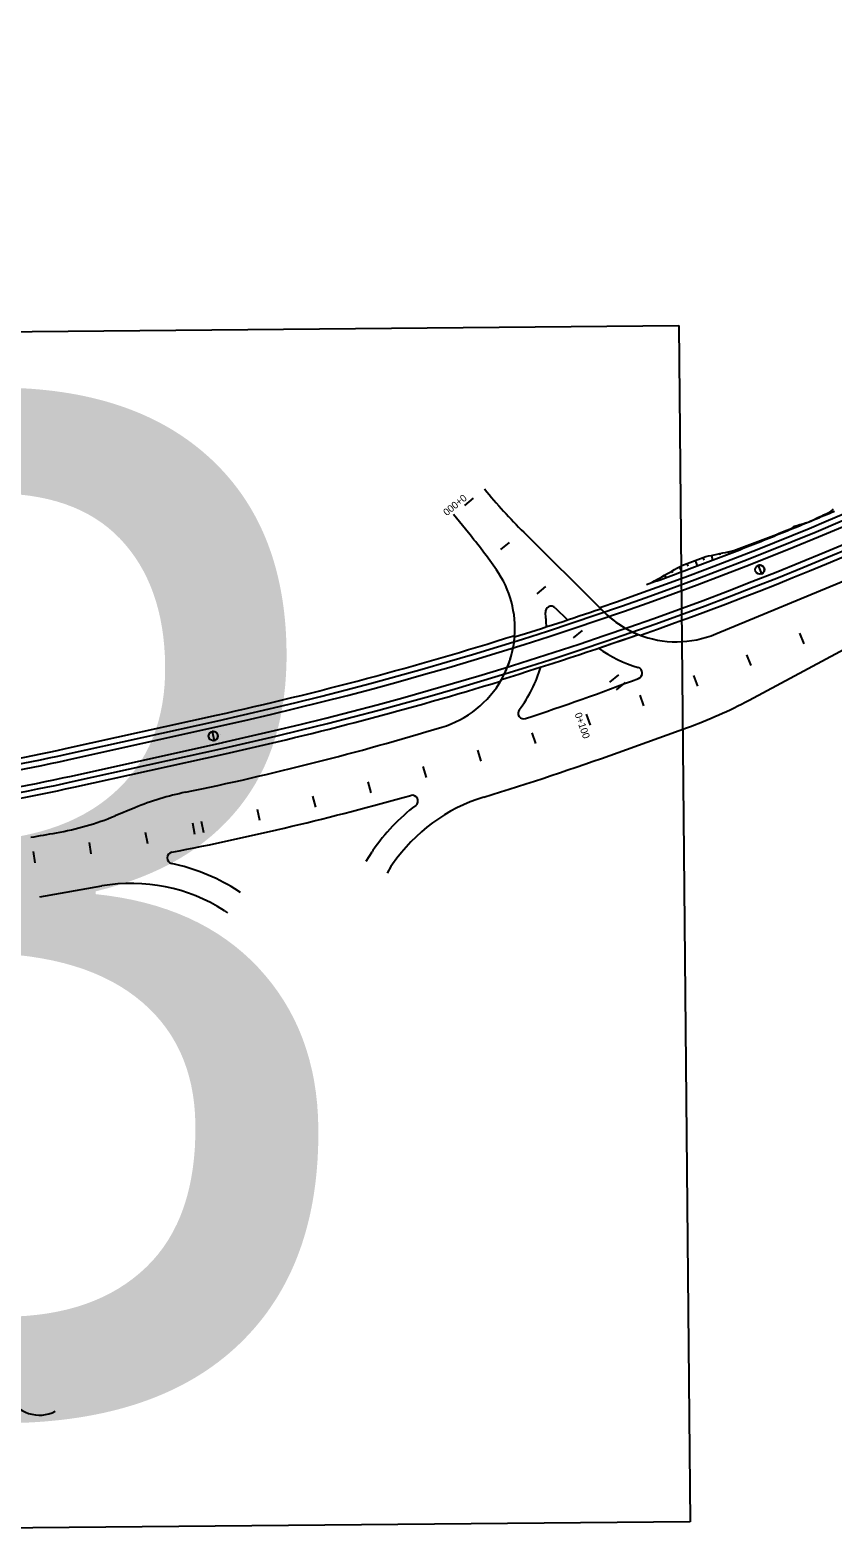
# Model space of a CAD drawing. Extents: x 6503541 to 6503743, y 5888004 to 5888145.
# Drawn here: x 6503677.06 to 6503680.42, y 5888078.09 to 5888084.41 of the extents above; entities that cross this region are included whole.
import ezdxf

# ---------------------------------------------------------------- set-up
doc = ezdxf.new("R2010")
doc.units = 0
doc.layers.add('12', color=7, linetype='Continuous')
doc.layers.add('tabela', color=7, linetype='Continuous')

msp = doc.modelspace()

# ---------------------------------------------------------------- linework, layer by layer
at = {"layer": '12'}
for p, q in [((6503678.8956, 5888082.3049), (6503678.8321, 5888082.3821)), ((6503680.3734, 5888082.3723), (6503680.3725, 5888082.3745)), ((6503680.4059, 5888082.3881), (6503680.4066, 5888082.3863)), ((6503680.2226, 5888082.3114), (6503680.2221, 5888082.3125)), ((6503680.2553, 5888082.3263), (6503680.2563, 5888082.3238)), ((6503680.2884, 5888082.3388), (6503680.2879, 5888082.3403)), ((6503680.3209, 5888082.3504), (6503680.3209, 5888082.3504)), ((6503679.1275, 5888082.3076), (6503679.4502, 5888081.987)), ((6503680.0541, 5888082.2479), (6503680.0558, 5888082.2434)), ((6503680.0886, 5888082.2586), (6503680.0878, 5888082.2606)), ((6503680.1214, 5888082.2735), (6503680.1228, 5888082.2699)), ((6503680.1556, 5888082.2848), (6503680.155, 5888082.2864)), ((6503680.1886, 5888082.2994), (6503680.1896, 5888082.2967)), ((6503679.8468, 5888082.1894), (6503679.8553, 5888082.1664)), ((6503679.8842, 5888082.1903), (6503679.8805, 5888082.2019)), ((6503679.9153, 5888082.211), (6503679.92, 5888082.1909)), ((6503679.9521, 5888082.2111), (6503679.9505, 5888082.2184)), ((6503679.9857, 5888082.226), (6503679.9879, 5888082.2169)), ((6503680.0212, 5888082.2327), (6503680.0204, 5888082.2352)), ((6503679.7175, 5888082.1271), (6503679.723, 5888082.1173)), ((6503679.753, 5888082.1374), (6503679.7488, 5888082.1449)), ((6503679.7801, 5888082.1627), (6503679.7903, 5888082.1421)), ((6503679.8176, 5888082.1654), (6503679.813, 5888082.1769)), ((6503679.6874, 5888082.1071), (6503679.6861, 5888082.1094)), ((6503679.9332, 5888081.8811), (6503680.4945, 5888082.1135)), ((6503679.259, 5888081.9908), (6503679.3104, 5888081.9398)), ((6503679.4502, 5888081.987), (6503679.4644, 5888081.9728)), ((6503679.4502, 5888081.987), (6503679.4626, 5888081.9746)), ((6503679.4502, 5888081.987), (6503679.4634, 5888081.9738)), ((6503680.0728, 5888081.6033), (6503680.5923, 5888081.8819)), ((6503677.2039, 5888081.3999), (6503677.8386, 5888081.5403)), ((6503677.2091, 5888081.3764), (6503677.8438, 5888081.5169)), ((6503677.2143, 5888081.353), (6503677.849, 5888081.4935)), ((6503679.5231, 5888081.3838), (6503679.8144, 5888081.4884)), ((6503677.2293, 5888081.285), (6503677.864, 5888081.4255)), ((6503677.2345, 5888081.2616), (6503677.8692, 5888081.4021)), ((6503677.2397, 5888081.2382), (6503677.8744, 5888081.3787)), ((6503677.4958, 5888081.1518), (6503677.4127, 5888081.1178)), ((6503678.4667, 5888080.9283), (6503678.4908, 5888080.9675)), ((6503678.4942, 5888080.9725), (6503678.4908, 5888080.9675)), ((6503678.5701, 5888080.905), (6503678.5539, 5888080.8773)), ((6503678.5773, 5888080.9154), (6503678.5701, 5888080.905)), ((6503677.097, 5888080.7782), (6503677.357, 5888080.8237)), ((6503677.9389, 5888080.7964), (6503677.9148, 5888080.8114)), ((6503677.8717, 5888080.7194), (6503677.8711, 5888080.7197)), ((6503677.8717, 5888080.7194), (6503677.8841, 5888080.7114))]:
    msp.add_line(p, q, dxfattribs=at)
for points in [[(6503678.9155, 5888082.4508), (6503678.8785, 5888082.4203)], [(6503679.6431, 5888082.0884), (6503679.6543, 5888082.0924), (6503679.6655, 5888082.0965), (6503679.6767, 5888082.1005), (6503679.6879, 5888082.1046), (6503679.6991, 5888082.1086), (6503679.7103, 5888082.1127), (6503679.7215, 5888082.1168), (6503679.7327, 5888082.1209), (6503679.7439, 5888082.125), (6503679.7551, 5888082.1291), (6503679.7663, 5888082.1332), (6503679.7774, 5888082.1373), (6503679.7886, 5888082.1415), (6503679.7998, 5888082.1456), (6503679.811, 5888082.1498), (6503679.8221, 5888082.1539), (6503679.8333, 5888082.1581), (6503679.8444, 5888082.1623), (6503679.8556, 5888082.1665), (6503679.8667, 5888082.1707), (6503679.8779, 5888082.1749), (6503679.889, 5888082.1791), (6503679.9002, 5888082.1833), (6503679.9113, 5888082.1875), (6503679.9224, 5888082.1918), (6503679.9336, 5888082.196), (6503679.9447, 5888082.2003), (6503679.9558, 5888082.2046), (6503679.9669, 5888082.2088), (6503679.978, 5888082.2131), (6503679.9891, 5888082.2174), (6503680.0003, 5888082.2217), (6503680.0114, 5888082.226), (6503680.0225, 5888082.2304), (6503680.0336, 5888082.2347), (6503680.0447, 5888082.239), (6503680.0557, 5888082.2434), (6503680.0668, 5888082.2477), (6503680.0779, 5888082.2521), (6503680.089, 5888082.2565), (6503680.1001, 5888082.2609), (6503680.1111, 5888082.2653), (6503680.1222, 5888082.2697), (6503680.1333, 5888082.2741), (6503680.1443, 5888082.2785), (6503680.1554, 5888082.2829), (6503680.1665, 5888082.2874), (6503680.1775, 5888082.2918), (6503680.1886, 5888082.2963), (6503680.1996, 5888082.3007), (6503680.2107, 5888082.3052), (6503680.2217, 5888082.3097), (6503680.2327, 5888082.3142), (6503680.2438, 5888082.3187), (6503680.2548, 5888082.3232), (6503680.2658, 5888082.3277), (6503680.2768, 5888082.3322), (6503680.2878, 5888082.3368), (6503680.2989, 5888082.3413), (6503680.3099, 5888082.3458), (6503680.3209, 5888082.3504), (6503680.3319, 5888082.355), (6503680.3429, 5888082.3596), (6503680.3539, 5888082.3641), (6503680.3649, 5888082.3687), (6503680.3758, 5888082.3733), (6503680.3868, 5888082.378), (6503680.3978, 5888082.3826)], [(6503680.3209, 5888082.3504), (6503680.3317, 5888082.3554), (6503680.3425, 5888082.3605), (6503680.3533, 5888082.3655), (6503680.3641, 5888082.3706), (6503680.3749, 5888082.3756), (6503680.3857, 5888082.3807), (6503680.3965, 5888082.3858), (6503680.4073, 5888082.3908), (6503680.4126, 5888082.3936)], [(6503680.3978, 5888082.3826), (6503680.4088, 5888082.3872), (6503680.4198, 5888082.3918), (6503680.4307, 5888082.3965)], [(6503680.4126, 5888082.3936), (6503680.4179, 5888082.3963), (6503680.4272, 5888082.4049)], [(6503679.6541, 5888082.093), (6503679.6651, 5888082.0976), (6503679.6757, 5888082.1035), (6503679.6862, 5888082.1095), (6503679.6967, 5888082.1154), (6503679.7072, 5888082.1213), (6503679.7177, 5888082.1272), (6503679.7282, 5888082.1332), (6503679.7387, 5888082.1391), (6503679.7492, 5888082.1451), (6503679.7597, 5888082.1511), (6503679.7702, 5888082.157), (6503679.7806, 5888082.163), (6503679.7911, 5888082.1689), (6503679.8023, 5888082.173), (6503679.8135, 5888082.1771), (6503679.8246, 5888082.1812), (6503679.8358, 5888082.1853), (6503679.847, 5888082.1894), (6503679.8581, 5888082.1936), (6503679.8692, 5888082.1977), (6503679.8804, 5888082.2019), (6503679.8916, 5888082.206), (6503679.9033, 5888082.2084), (6503679.9151, 5888082.2109), (6503679.9269, 5888082.2134), (6503679.9387, 5888082.2159), (6503679.9505, 5888082.2184), (6503679.9623, 5888082.2209), (6503679.974, 5888082.2235), (6503679.9858, 5888082.226), (6503679.9976, 5888082.2286), (6503680.0094, 5888082.2311), (6503680.0206, 5888082.2353), (6503680.0317, 5888082.2394), (6503680.0429, 5888082.2436), (6503680.054, 5888082.2478), (6503680.0651, 5888082.252), (6503680.0763, 5888082.2563), (6503680.0874, 5888082.2605), (6503680.0985, 5888082.2647), (6503680.1097, 5888082.269), (6503680.1208, 5888082.2732), (6503680.1319, 5888082.2775), (6503680.143, 5888082.2818), (6503680.1542, 5888082.286), (6503680.1653, 5888082.2903), (6503680.1764, 5888082.2946), (6503680.1875, 5888082.299), (6503680.1986, 5888082.3033), (6503680.2097, 5888082.3076), (6503680.2208, 5888082.3119), (6503680.2319, 5888082.3163), (6503680.243, 5888082.3206), (6503680.254, 5888082.3252), (6503680.2636, 5888082.333), (6503680.2751, 5888082.3364), (6503680.2865, 5888082.3399), (6503680.298, 5888082.3434), (6503680.3094, 5888082.3469), (6503680.3209, 5888082.3504)], [(6503679.031, 5888082.235), (6503679.0681, 5888082.2655)], [(6503680.1108, 5888082.1688), (6503680.1248, 5888082.1331)], [(6503679.1836, 5888082.0497), (6503679.2207, 5888082.0803)], [(6503679.3361, 5888081.8645), (6503679.3732, 5888081.895)], [(6503680.3043, 5888081.8402), (6503680.2856, 5888081.8844)], [(6503680.0818, 5888081.7489), (6503680.0641, 5888081.7935)], [(6503679.4887, 5888081.6792), (6503679.5258, 5888081.7097)], [(6503679.5524, 5888081.6774), (6503679.5153, 5888081.6469)], [(6503679.8576, 5888081.6621), (6503679.8407, 5888081.707)], [(6503679.6318, 5888081.5796), (6503679.6156, 5888081.6248)], [(6503679.3898, 5888081.5439), (6503679.4058, 5888081.4987)], [(6503677.8202, 5888081.4711), (6503677.8285, 5888081.4336)], [(6503679.1782, 5888081.4209), (6503679.1631, 5888081.4664)], [(6503678.9493, 5888081.3475), (6503678.935, 5888081.3933)], [(6503678.7189, 5888081.2785), (6503678.7056, 5888081.3246)], [(6503678.4873, 5888081.2139), (6503678.4748, 5888081.2603)], [(6503678.2544, 5888081.1538), (6503678.2429, 5888081.2004)], [(6503678.0205, 5888081.0982), (6503678.0099, 5888081.145)], [(6503677.5496, 5888081.0006), (6503677.5408, 5888081.0478)], [(6503677.7479, 5888081.0399), (6503677.7391, 5888081.0871)], [(6503677.7855, 5888081.0472), (6503677.7758, 5888081.0942)], [(6503677.3129, 5888080.9586), (6503677.3049, 5888081.0059)], [(6503677.0683, 5888080.9686), (6503677.0754, 5888080.9211)]]:
    msp.add_lwpolyline(points, dxfattribs=at)
for centre in [(6503680.1178, 5888082.151), (6503677.8244, 5888081.4524)]:
    msp.add_circle(centre, 0.0192, dxfattribs=at)
for centre, radius, start, end in [((6503674.6145, 5888096.105), 14.9412, 282.48188, 335.91738), ((6503674.6145, 5888096.105), 14.9652, 282.48188, 335.91738), ((6503674.6145, 5888096.105), 15.0348, 282.48188, 335.91738), ((6503674.6145, 5888096.105), 15.0588, 282.48188, 335.91738), ((6503674.6145, 5888096.105), 14.9172, 288.89877, 308.11483), ((6503674.6145, 5888096.105), 15.0828, 289.37027, 307.81474), ((6503680.8193, 5888084.0099), 2.4, 219.31239, 225.17753), ((6503677.0428, 5888080.7794), 2.4, 34.82086, 39.46694), ((6503678.6584, 5888081.9032), 0.432, 355.3769, 34.82086), ((6503680.1178, 5888082.151), 0.0192, 347.07645, 111.52368), ((6503680.1178, 5888082.151), 0.0192, 291.52368, 347.07645), ((6503679.2421, 5888081.9738), 0.024, 45.17753, 186.90027), ((6503679.7672, 5888082.281), 0.432, 222.00494, 249.66641), ((6503674.6145, 5888096.105), 14.9232, 287.44754, 288.90731), ((6503674.6145, 5888096.105), 14.9232, 287.44754, 288.90731), ((6503678.6584, 5888081.9032), 0.564, 0.7904, 6.90027), ((6503679.768, 5888082.2802), 0.432, 225.17753, 248.23474), ((6503674.6145, 5888096.105), 14.9172, 282.48188, 287.45669), ((6503678.6584, 5888081.9032), 0.432, 329.35412, 356.23305), ((6503674.6145, 5888096.105), 15.0768, 287.04736, 289.34339), ((6503674.6145, 5888096.105), 15.0768, 287.04736, 289.34087), ((6503678.6584, 5888081.9032), 0.432, 330.52309, 355.3769), ((6503679.768, 5888082.2802), 0.432, 248.23474, 292.49122), ((6503679.7672, 5888082.281), 0.564, 234.58535, 253.55389), ((6503678.6584, 5888081.9032), 0.564, 322.91658, 343.39971), ((6503679.6007, 5888081.7171), 0.024, 290.75597, 73.55389), ((6503674.6145, 5888096.105), 15.0828, 282.48188, 287.02283), ((6503678.6584, 5888081.9032), 0.432, 286.82524, 330.52309), ((6503675.2162, 5888093.2861), 12.396, 288.42954, 290.75597), ((6503675.2162, 5888093.2861), 12.396, 288.42954, 290.75597), ((6503679.1275, 5888081.5486), 0.024, 142.91658, 288.42954), ((6503679.1654, 5888083.2954), 1.92, 289.75621, 298.20181), ((6503675.2162, 5888093.2861), 12.324, 281.66639, 286.82524), ((6503677.8244, 5888081.4524), 0.0192, 338.03464, 102.48188), ((6503677.8244, 5888081.4524), 0.0192, 282.48188, 338.03464), ((6503675.6657, 5888088.3488), 7.1412, 272.95394, 282.48188), ((6503675.6645, 5888088.3538), 7.1223, 273.51736, 282.48188), ((6503675.2466, 5888093.2907), 12.6516, 287.06608, 289.75621), ((6503675.6657, 5888088.3488), 7.1652, 272.95394, 282.48188), ((6503675.6657, 5888088.3488), 7.2348, 272.95394, 282.48188), ((6503675.6657, 5888088.3488), 7.2588, 272.95394, 282.48188), ((6503675.6657, 5888088.3488), 7.2828, 273.57139, 282.48188), ((6503677.9509, 5888080.0415), 1.2, 101.66639, 112.28688), ((6503675.2466, 5888093.2907), 12.558, 281.03427, 285.73926), ((6503679.1708, 5888080.5079), 0.72, 107.06608, 145.52266), ((6503678.6596, 5888081.1804), 0.024, 307.23962, 105.73926), ((6503676.9576, 5888082.2281), 1.2, 280.00627, 292.28688), ((6503679.1708, 5888080.5079), 0.8208, 127.23962, 145.52266), ((6503674.1365, 5888098.2171), 17.436, 279.65062, 280.00627), ((6503677.6548, 5888080.9413), 0.024, 101.03427, 258.13958), ((6503677.4811, 5888080.1145), 0.8208, 58.10446, 78.13958), ((6503677.4811, 5888080.1145), 0.72, 57.20304, 99.92715), ((6503677.095, 5888078.7471), 0.144, 205.67836, 297.61406)]:
    msp.add_arc(centre, radius, start, end, dxfattribs=at)
at = {"layer": 'tabela'}
for p, q in [((6503672.5429, 5888083.1083), (6503679.7783, 5888083.1758)), ((6503672.5429, 5888083.1083), (6503679.7783, 5888083.1758)), ((6503679.7783, 5888083.1758), (6503679.8252, 5888078.1557)), ((6503679.7783, 5888083.1758), (6503679.8252, 5888078.1557)), ((6503679.8252, 5888078.1557), (6503672.5898, 5888078.0882)), ((6503679.8252, 5888078.1557), (6503672.5898, 5888078.0882))]:
    msp.add_line(p, q, dxfattribs=at)

# ---------------------------------------------------------------- texts
at = {"layer": '12'}
for s, height, rotation, p in [('13', 4.22297, 0.73934, (6503672.2478, 5888078.5685)), ('0+000', 0.03, 219.46694, (6503678.8725, 5888082.4695)), ('0+100', 0.03, 289.42821, (6503679.3405, 5888081.545)), ('C', 0.0024, 12.48188, (6503677.8556, 5888081.4581)), ('C', 0.0024, 12.48188, (6503677.2209, 5888081.3176))]:
    msp.add_text(s, height=height, rotation=rotation, dxfattribs=at).set_placement(p)

doc.saveas('drawing.dxf')
